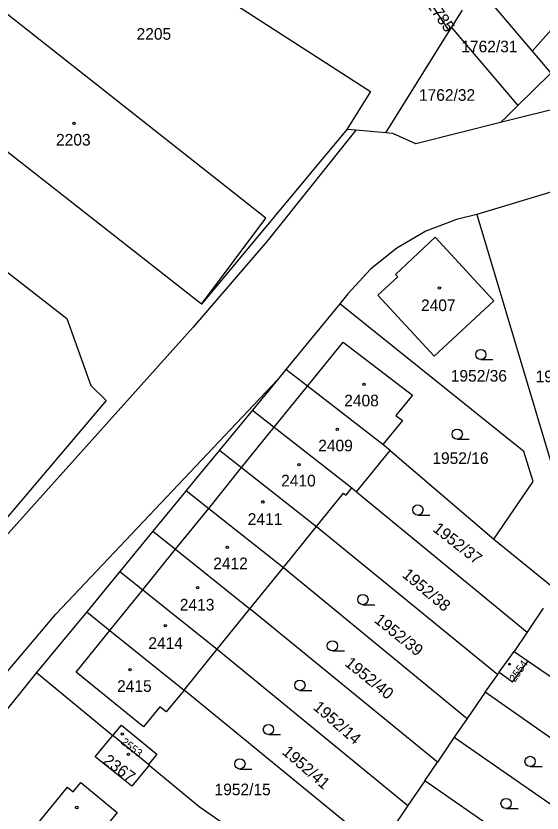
# Model space of a CAD drawing. Extents: x -679220 to -673243, y -1075091 to -1066557.
# Drawn here: x -676725.7 to -676648.8, y -1072700.8 to -1072584.3 of the extents above; entities that cross this region are included whole.
import ezdxf

# ---------------------------------------------------------------- set-up
doc = ezdxf.new("R2010")
doc.units = 0
for name, color, linetype in [('Hranice parcel', 7, 'Continuous'), ('Parcelní čísla', 7, 'Continuous'), ('Vnitřní kresba', 7, 'Continuous'), ('Značky budov', 7, 'Continuous'), ('Značky kultur', 7, 'Continuous')]:
    doc.layers.add(name, color=color, linetype=linetype)

msp = doc.modelspace()

# ---------------------------------------------------------------- linework, layer by layer
at = {"layer": 'Hranice parcel'}
for p, q in [((-676658.3, -1072579.97), (-676650.25, -1072589.43)), ((-676662.04, -1072585.98), (-676660.46, -1072583.45)), ((-676671.63, -1072601.38), (-676662.37, -1072586.52)), ((-676662.37, -1072586.52), (-676662.04, -1072585.98)), ((-676662.04, -1072585.98), (-676652.34, -1072597.37)), ((-676698.62, -1072626.39), (-676746.87, -1072588.6)), ((-676650.25, -1072589.43), (-676647.52, -1072592.64)), ((-676652.34, -1072597.37), (-676647.52, -1072592.64)), ((-676677.35, -1072600.85), (-676698.62, -1072626.39)), ((-676676.04, -1072600.97), (-676677.35, -1072600.85)), ((-676671.63, -1072601.38), (-676676.04, -1072600.97)), ((-676646.88, -1072609.85), (-676658.37, -1072613.31)), ((-676678.37, -1072626.34), (-676686.26, -1072635.94)), ((-676686.26, -1072635.94), (-676687.51, -1072637.46)), ((-676683.1, -1072638.39), (-676686.26, -1072635.94)), ((-676687.51, -1072637.46), (-676691.16, -1072641.89)), ((-676672.09, -1072646.93), (-676683.1, -1072638.39)), ((-676691.16, -1072641.89), (-676695.98, -1072647.74)), ((-676671.03, -1072647.78), (-676672.09, -1072646.93)), ((-676695.98, -1072647.74), (-676700.83, -1072653.64)), ((-676675.93, -1072653.82), (-676671.03, -1072647.78)), ((-676671.03, -1072647.78), (-676655.85, -1072660.75)), ((-676676.61, -1072653.26), (-676675.93, -1072653.82)), ((-676675.93, -1072653.82), (-676651.01, -1072674.34)), ((-676686.64, -1072664.89), (-676681.78, -1072658.91)), ((-676681.78, -1072658.91), (-676655.3, -1072680.5)), ((-676705.71, -1072659.57), (-676710.54, -1072665.45)), ((-676655.85, -1072660.75), (-676646.81, -1072668.09)), ((-676691.52, -1072670.91), (-676686.64, -1072664.89)), ((-676686.64, -1072664.89), (-676659.76, -1072686.94)), ((-676710.54, -1072665.45), (-676715.39, -1072671.34)), ((-676715.39, -1072671.34), (-676722.71, -1072680.24)), ((-676715.39, -1072671.34), (-676712, -1072674.07)), ((-676696.31, -1072676.81), (-676691.52, -1072670.91)), ((-676664.1, -1072693.32), (-676691.52, -1072670.91)), ((-676648.64, -1072670.81), (-676651.01, -1072674.34)), ((-676712, -1072674.07), (-676701.16, -1072682.79)), ((-676651.01, -1072674.34), (-676652.91, -1072677.17)), ((-676701.16, -1072682.79), (-676696.31, -1072676.81)), ((-676696.31, -1072676.81), (-676668.42, -1072699.67)), ((-676655.08, -1072680.2), (-676652.91, -1072677.17)), ((-676652.91, -1072677.17), (-676650.84, -1072678.59)), ((-676650.84, -1072678.59), (-676628.01, -1072694.22)), ((-676722.71, -1072680.24), (-676740.22, -1072701.84)), ((-676722.71, -1072680.24), (-676711.56, -1072689.42)), ((-676657.14, -1072683.09), (-676655.3, -1072680.5)), ((-676655.3, -1072680.5), (-676655.08, -1072680.2)), ((-676672.74, -1072706.03), (-676701.16, -1072682.79)), ((-676657.14, -1072683.09), (-676659.76, -1072686.94)), ((-676632.33, -1072700.52), (-676657.14, -1072683.09)), ((-676659.76, -1072686.94), (-676661.64, -1072689.7)), ((-676706.38, -1072693.69), (-676711.56, -1072689.42)), ((-676661.64, -1072689.7), (-676664.1, -1072693.32)), ((-676661.64, -1072689.7), (-676636.67, -1072707.03)), ((-676706.38, -1072693.69), (-676706.26, -1072693.79)), ((-676665.95, -1072696.04), (-676664.1, -1072693.32)), ((-676665.95, -1072696.04), (-676668.42, -1072699.67)), ((-676641, -1072713.4), (-676665.95, -1072696.04)), ((-676668.42, -1072699.67), (-676672.74, -1072706.03))]:
    msp.add_line(p, q, dxfattribs=at)
for points in [[(-676600.72, -1072503.07), (-676606.15, -1072509.65), (-676615.52, -1072525.52), (-676623.12, -1072540.2), (-676630.2, -1072558.24), (-676644.99, -1072583.54), (-676650.25, -1072589.43)], [(-676700.41, -1072559.6), (-676708.95, -1072572.72), (-676673.88, -1072595.32), (-676677.35, -1072600.85)], [(-676698.62, -1072626.39), (-676689.21, -1072613.81), (-676730.8, -1072581.05)], [(-676665.86, -1072581.78), (-676665.32, -1072582.13), (-676662.37, -1072586.52)], [(-676593.34, -1072586.97), (-676606.98, -1072590.41), (-676644.92, -1072597.35), (-676654.89, -1072599.85)], [(-676652.34, -1072597.37), (-676654, -1072599), (-676654.89, -1072599.85)], [(-676654.89, -1072599.85), (-676667.29, -1072602.95), (-676670.65, -1072601.47), (-676671.63, -1072601.38)], [(-676676.04, -1072600.97), (-676689.01, -1072617.2), (-676699.82, -1072629.74), (-676727.69, -1072660.82), (-676752.08, -1072697.33), (-676758.72, -1072705.55), (-676780.51, -1072731.52), (-676784.98, -1072736.24)], [(-676658.37, -1072613.31), (-676661.32, -1072614.01), (-676665.79, -1072615.73), (-676670.06, -1072618.2), (-676673.91, -1072621.29), (-676677.19, -1072624.91), (-676678.37, -1072626.34)], [(-676658.37, -1072613.31), (-676646.9, -1072651.58), (-676635.58, -1072647.85)], [(-676670.26, -1072622.05), (-676664.42, -1072616.63), (-676655.85, -1072625.91), (-676664.59, -1072634.02), (-676672.84, -1072625.09), (-676669.91, -1072622.38), (-676670.26, -1072622.05)], [(-676730.94, -1072618.7), (-676718.3, -1072628.48), (-676714.8, -1072638.27), (-676712.57, -1072640.47), (-676739.84, -1072672.64)], [(-676655.85, -1072660.75), (-676650.12, -1072652.3), (-676651.5, -1072647.93), (-676678.37, -1072626.34)], [(-676683.1, -1072638.39), (-676677.9, -1072631.96), (-676667.76, -1072639.68), (-676670.17, -1072642.65), (-676669.23, -1072643.41), (-676672.09, -1072646.93)], [(-676744.49, -1072706.81), (-676742.71, -1072698.63), (-676719.91, -1072671.69), (-676687.51, -1072637.46)], [(-676691.16, -1072641.89), (-676687.96, -1072644.39), (-676676.61, -1072653.26)], [(-676695.98, -1072647.74), (-676692.74, -1072650.29), (-676681.78, -1072658.91)], [(-676681.78, -1072658.91), (-676677.82, -1072654.03), (-676677.47, -1072654.32), (-676676.61, -1072653.26)], [(-676700.83, -1072653.64), (-676700.95, -1072653.78), (-676705.71, -1072659.57)], [(-676700.83, -1072653.64), (-676697.55, -1072656.24), (-676686.64, -1072664.89)], [(-676705.71, -1072659.57), (-676702.4, -1072662.22), (-676691.52, -1072670.91)], [(-676710.54, -1072665.45), (-676707.18, -1072668.13), (-676696.31, -1072676.81)], [(-676701.16, -1072682.79), (-676703.76, -1072685.99), (-676704.7, -1072685.23), (-676707.08, -1072688.16), (-676716.94, -1072680.17), (-676712, -1072674.07)], [(-676655.08, -1072680.2), (-676653.14, -1072681.59), (-676650.84, -1072678.59)], [(-676711.56, -1072689.42), (-676710.32, -1072687.92), (-676705.12, -1072692.17), (-676706.38, -1072693.69)], [(-676706.26, -1072693.79), (-676708.79, -1072696.86), (-676714.14, -1072692.55), (-676711.56, -1072689.42)], [(-676706.26, -1072693.79), (-676698.95, -1072699.81), (-676684.06, -1072710.13)], [(-676716.41, -1072707.37), (-676722.56, -1072702.31), (-676718.18, -1072697), (-676717.39, -1072697.65), (-676716.27, -1072696.3), (-676710.92, -1072700.7), (-676716.41, -1072707.37)]]:
    msp.add_lwpolyline(points, dxfattribs=at)
at = {"layer": 'Vnitřní kresba'}
for p, q in [((-676687.96, -1072644.39), (-676683.1, -1072638.39)), ((-676692.74, -1072650.29), (-676687.96, -1072644.39)), ((-676697.55, -1072656.24), (-676692.74, -1072650.29)), ((-676702.4, -1072662.22), (-676697.55, -1072656.24)), ((-676707.18, -1072668.13), (-676702.4, -1072662.22)), ((-676712, -1072674.07), (-676707.18, -1072668.13))]:
    msp.add_line(p, q, dxfattribs=at)
at = {"layer": 'Značky budov'}
for centre, radius in [((-676717.26, -1072599.95), 0.175), ((-676663.81, -1072624.04), 0.175), ((-676674.84, -1072638.11), 0.175), ((-676678.75, -1072644.69), 0.175), ((-676684.37, -1072649.84), 0.175), ((-676689.64, -1072655.29), 0.175), ((-676694.85, -1072661.92), 0.175), ((-676699.17, -1072667.84), 0.175), ((-676703.9, -1072673.4), 0.175), ((-676653.57, -1072679.01), 0.117), ((-676709.05, -1072679.83), 0.175), ((-676710.2, -1072689.21), 0.175), ((-676709.3, -1072692.18), 0.175), ((-676716.84, -1072699.96), 0.175)]:
    msp.add_circle(centre, radius, dxfattribs=at)
at = {"layer": 'Značky kultur'}
for p, q in [((-676657.76, -1072634.5), (-676656.01, -1072634.5)), ((-676661.21, -1072646.15), (-676659.46, -1072646.15)), ((-676666.96, -1072657.23), (-676665.21, -1072657.23)), ((-676675.01, -1072670.32), (-676673.26, -1072670.32)), ((-676679.47, -1072677.08), (-676677.72, -1072677.08)), ((-676684.22, -1072682.84), (-676682.47, -1072682.84)), ((-676688.82, -1072689.31), (-676687.07, -1072689.31)), ((-676650.56, -1072693.98), (-676648.81, -1072693.98)), ((-676692.99, -1072694.34), (-676691.24, -1072694.34)), ((-676654.07, -1072700.13), (-676652.32, -1072700.13))]:
    msp.add_line(p, q, dxfattribs=at)
for centre in [(-676657.76, -1072633.75), (-676661.21, -1072645.4), (-676666.96, -1072656.48), (-676675.01, -1072669.57), (-676679.47, -1072676.33), (-676684.22, -1072682.09), (-676688.82, -1072688.56), (-676692.99, -1072693.59), (-676650.56, -1072693.23), (-676654.07, -1072699.38)]:
    msp.add_circle(centre, 0.75, dxfattribs=at)

# ---------------------------------------------------------------- texts
at = {"layer": 'Parcelní čísla'}
for s, height, rotation, p in [('1785', 1.7, 305, (-676665.75, -1072582.67)), ('1952/37', 1.7, 322, (-676664.91, -1072659.48)), ('1952/38', 1.7, 320, (-676669.39, -1072666.15)), ('1952/39', 1.7, 321, (-676673.47, -1072672.78)), ('1952/40', 1.7, 321, (-676677.78, -1072679.11)), ('2554', 1.14, 55, (-676652.78, -1072681.72)), ('1952/14', 1.7, 319, (-676682.41, -1072685.49)), ('2553', 1.14, 322, (-676710.47, -1072690.57)), ('1952/41', 1.7, 319, (-676686.94, -1072692.03)), ('2367', 1.7, 323, (-676713.15, -1072693.39))]:
    msp.add_text(s, height=height, rotation=rotation, dxfattribs=at).set_placement(p)
for s, p in [('2205', (-676708.1, -1072587.75)), ('1762/31', (-676660.62, -1072589.59)), ('1762/32', (-676666.81, -1072596.68)), ('2203', (-676719.88, -1072603.22)), ('2407', (-676666.51, -1072627.41)), ('1952/36', (-676662.16, -1072637.72)), ('1952/35', (-676649.75, -1072637.8)), ('2408', (-676677.74, -1072641.33)), ('2409', (-676681.54, -1072647.91)), ('1952/16', (-676664.85, -1072649.75)), ('2410', (-676686.96, -1072653.04)), ('2411', (-676691.85, -1072658.65)), ('2412', (-676696.89, -1072665.13)), ('2413', (-676701.78, -1072671.17)), ('2414', (-676706.38, -1072676.78)), ('2415', (-676710.95, -1072683.06)), ('1952/15', (-676696.7, -1072698.17))]:
    msp.add_text(s, height=1.7, dxfattribs=at).set_placement(p)

doc.saveas('drawing.dxf')
